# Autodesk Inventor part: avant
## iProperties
Created: 2011-01
Part Number: avant
Document SubType Name: Modeling
Designer: eric
Density: 1 g/cm^3
Mass: 10.5448 g
Surface Area: 151.038 cm^2
Volume: 10.5448 cm^3
Author: eric
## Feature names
1. Base1
